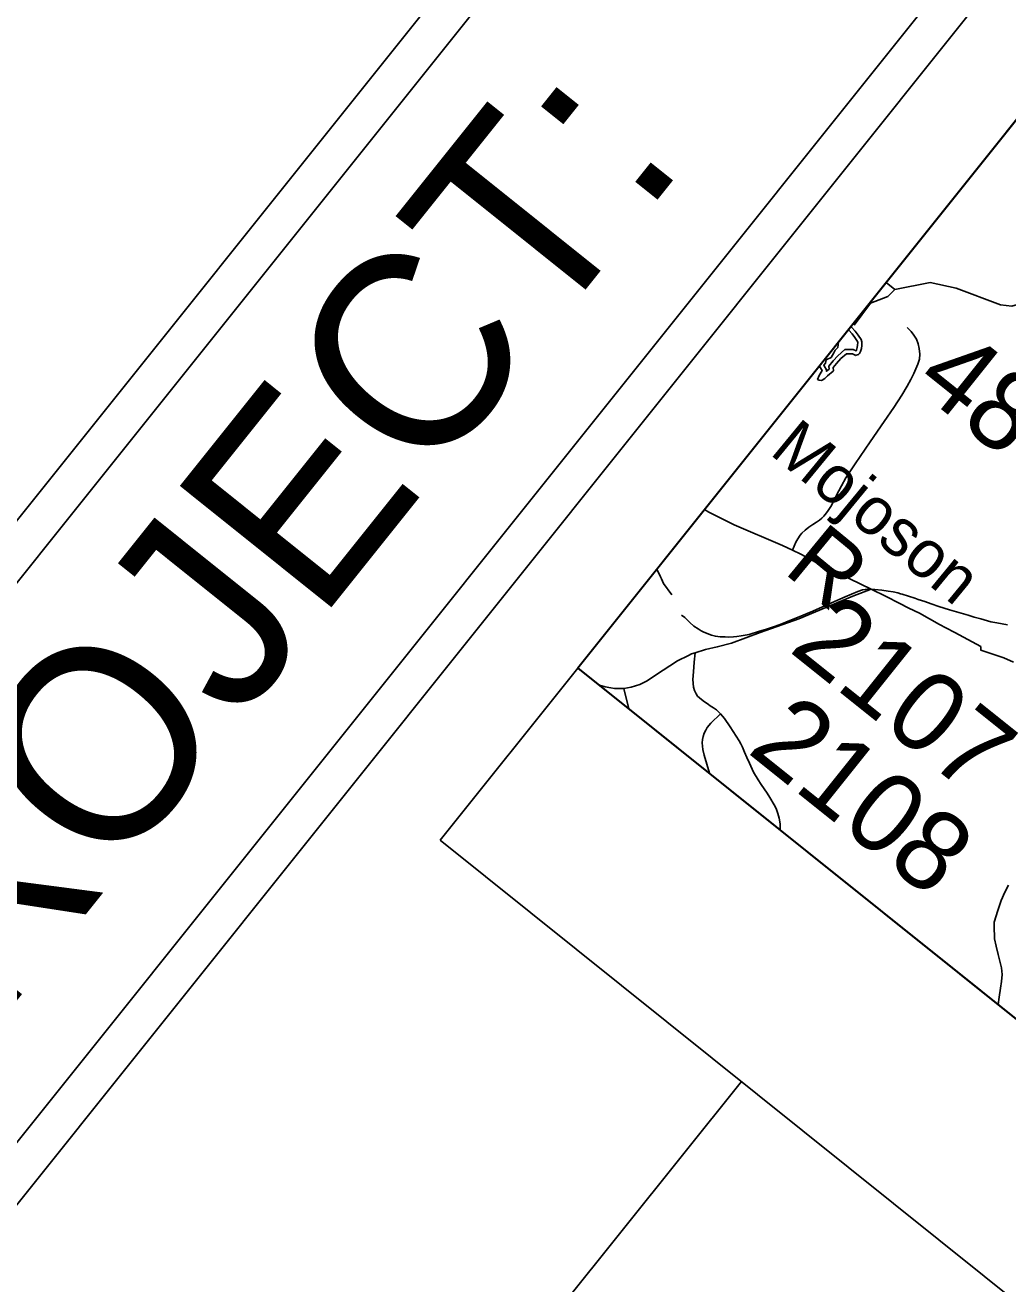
# Model space of a CAD drawing. Extents: x 1732765 to 1738218, y 913652 to 917906.
# Drawn here: x 1733949.3 to 1734202.3, y 916756.7 to 917080.6 of the extents above; entities that cross this region are included whole.
import ezdxf

# ---------------------------------------------------------------- set-up
doc = ezdxf.new("R2010")
doc.units = 0
for name, color, linetype in [('Old_Level_28', 7, 'Continuous'), ('Old_Level_32', 7, 'Continuous'), ('Old_Level_34', 7, 'Continuous'), ('Old_Level_44', 7, 'Continuous'), ('Old_Level_48', 7, 'Continuous'), ('Old_Level_49', 7, 'Continuous'), ('Old_Level_59', 7, 'Continuous'), ('Old_Level_61', 7, 'Continuous'), ('Old_Level_8', 7, 'Continuous'), ('Sheet Title CELL', 7, 'Continuous')]:
    doc.layers.add(name, color=color, linetype=linetype)

msp = doc.modelspace()

# ---------------------------------------------------------------- linework, layer by layer
at = {"layer": 'Old_Level_28'}
for points in [[(1734124.18, 916955.89), (1734125.35, 916955.24), (1734131.89, 916952.02), (1734144.32, 916946.66), (1734146.88, 916945.47)], [(1734146.88, 916945.47), (1734149.04, 916944.47), (1734153.01, 916942.31), (1734155.94, 916940.88), (1734167.13, 916935.46)], [(1734167.13, 916935.46), (1734170.98, 916933.51), (1734174.31, 916931.87), (1734176.81, 916930.58), (1734179.56, 916929.22), (1734184.69, 916926.37), (1734186.39, 916925.52), (1734188.68, 916924.28), (1734195.34, 916920.68), (1734195.36, 916919.72), (1734201.24, 916917.77), (1734203.78, 916916.69)]]:
    msp.add_lwpolyline(points, dxfattribs=at)
at = {"layer": 'Old_Level_32'}
for points in [[(1734146.88, 916945.47), (1734147.77, 916947.51), (1734148.28, 916948.41), (1734148.85, 916949.3), (1734149.3, 916949.85), (1734150.11, 916950.6), (1734151.07, 916951.39), (1734152.09, 916952.04), (1734153.06, 916952.66), (1734153.82, 916953.22), (1734154.43, 916953.71), (1734154.96, 916954.23), (1734155.64, 916955.06), (1734156.05, 916955.64), (1734156.88, 916956.95), (1734158.15, 916959.46), (1734159.49, 916962.05), (1734160.61, 916964.05), (1734163.03, 916967.68), (1734166.84, 916973.35), (1734170.47, 916978.59), (1734172.99, 916982.15), (1734174.99, 916985.34), (1734176.36, 916987.64), (1734177.3, 916989.37), (1734178.09, 916990.92), (1734179.17, 916993.33), (1734179.53, 916994.63), (1734179.65, 916995.91), (1734179.51, 916997.34), (1734179.21, 916998.52), (1734178.76, 916999.77), (1734178.15, 917000.77), (1734177.39, 917001.72), (1734176.42, 917002.74)], [(1734121.86, 916919.09), (1734124.51, 916919.89), (1734127.52, 916920.57), (1734131.14, 916921.53), (1734138.55, 916924.28), (1734148.47, 916927.82), (1734162.42, 916933.62), (1734167.13, 916935.46)], [(1734103.44, 916909.84), (1734105.35, 916910.2), (1734107.54, 916910.88), (1734109.5, 916911.84), (1734111.64, 916913.29), (1734117.25, 916917), (1734120.06, 916918.38), (1734120.88, 916918.78), (1734121.86, 916919.09)], [(1734121.86, 916919.09), (1734121.6, 916916.64), (1734121.42, 916914.14), (1734121.25, 916912.23), (1734121.35, 916910.26), (1734121.66, 916909.34), (1734122.06, 916908.52), (1734122.44, 916907.93), (1734122.97, 916907.44), (1734123.91, 916906.68), (1734125.21, 916905.77), (1734125.69, 916905.45), (1734126.56, 916904.9), (1734127.33, 916904.35), (1734128.36, 916903.36)], [(1734097.18, 916910.71), (1734098.62, 916910.29), (1734100.13, 916910.01), (1734101.08, 916909.89), (1734103.44, 916909.84)], [(1734103.44, 916909.84), (1734104.77, 916904.64)], [(1734128.36, 916903.36), (1734125.82, 916900.99), (1734124.9, 916899.84), (1734124.54, 916899.15), (1734124.16, 916898.39), (1734123.91, 916897.51), (1734123.72, 916896.77), (1734123.66, 916895.86), (1734123.82, 916894.21), (1734124.16, 916892.68), (1734125.48, 916888.07)], [(1734128.36, 916903.36), (1734129.35, 916902.12), (1734130.79, 916899.99), (1734133.11, 916896.41), (1734133.57, 916895.64), (1734133.99, 916894.75), (1734134.48, 916893.51), (1734135.1, 916892.12), (1734135.81, 916890.66), (1734136.85, 916888.34), (1734138.03, 916886.36), (1734138.85, 916885.18), (1734140.32, 916882.93), (1734141, 916881.79), (1734142.13, 916879.91), (1734142.63, 916878.98), (1734143.07, 916877.71), (1734143.48, 916876.47), (1734143.7, 916875.03), (1734143.71, 916873.79), (1734143.68, 916873.5)], [(1734202.49, 916859.29), (1734201.55, 916857.49), (1734200.6, 916855.34), (1734199.71, 916852.79), (1734198.79, 916849.79), (1734198.78, 916847.92), (1734198.85, 916846.33), (1734198.89, 916845.45), (1734199.34, 916843.55), (1734199.79, 916841.41), (1734200.37, 916839.37), (1734200.68, 916838.04), (1734200.87, 916836.32), (1734200.66, 916834.52), (1734200.4, 916832.74), (1734200.12, 916830.49), (1734199.79, 916828.6)]]:
    msp.add_lwpolyline(points, dxfattribs=at)
at = {"layer": 'Old_Level_44'}
for points in [[(1734111.97, 916940.62), (1734112.91, 916938.57), (1734113.16, 916938.09), (1734113.66, 916936.9), (1734115.85, 916933.97)], [(1734202.21, 916926.28), (1734199.47, 916926.75), (1734197.92, 916926.99), (1734195.32, 916927.79), (1734193.68, 916928.23), (1734192.08, 916928.73), (1734189.08, 916929.59), (1734187.25, 916930.14), (1734184.52, 916930.99), (1734182.6, 916931.66), (1734180.92, 916932.27), (1734179.23, 916932.78), (1734178.39, 916933.09), (1734175.1, 916934.14), (1734174.71, 916934.27), (1734174, 916934.47), (1734172.8, 916934.74), (1734171.47, 916934.94), (1734169.85, 916935.19), (1734168.09, 916935.35), (1734166.99, 916935.42), (1734166.2, 916935.42), (1734165.64, 916935.37), (1734164.87, 916935.23), (1734163.73, 916934.87), (1734160.41, 916933.47), (1734156.93, 916931.94), (1734152.08, 916929.79), (1734148.18, 916928.15), (1734145.78, 916927.23), (1734144.14, 916926.51), (1734142.28, 916925.84), (1734139.94, 916925.05), (1734138.38, 916924.59), (1734135.71, 916923.81), (1734133.62, 916923.41), (1734132.53, 916923.27), (1734131.68, 916923.2), (1734130.31, 916923.11), (1734129.56, 916923.14), (1734128.24, 916923.13), (1734127.05, 916923.3), (1734126, 916923.56), (1734124.05, 916924.35), (1734123.34, 916924.74), (1734122.55, 916925.2), (1734121.46, 916925.92), (1734120.45, 916926.82), (1734119.67, 916927.6), (1734119.12, 916928.12), (1734118.32, 916928.72)]]:
    msp.add_lwpolyline(points, dxfattribs=at)
at = {"layer": 'Old_Level_48'}
msp.add_lwpolyline([(1734223.86, 917080.44), (1734091.6, 916915.18), (1734247.43, 916790.47)], dxfattribs=at)
at = {"layer": 'Old_Level_49'}
msp.add_lwpolyline([(1734223.86, 917080.44), (1734091.6, 916915.18), (1734247.43, 916790.47)], dxfattribs=at)
at = {"layer": 'Old_Level_59'}
for points in [[(1734162.71, 917003.4), (1734166.98, 917008.99), (1734171.41, 917010.71), (1734173.19, 917012.53)], [(1734170.99, 917014.38), (1734173.19, 917012.53)], [(1734173.19, 917012.53), (1734182.34, 917014.31), (1734188.97, 917012.84), (1734200.45, 917008.63), (1734203.33, 917008.21), (1734210.95, 917010.44), (1734214.2, 917012.08), (1734221.38, 917013.17), (1734227.05, 917013.07), (1734250.36, 917004.87)]]:
    msp.add_lwpolyline(points, dxfattribs=at)
at = {"layer": 'Old_Level_61'}
for points in [[(1734162.1, 917002.85), (1734163.05, 917001.79), (1734163.81, 917000.81), (1734164.54, 916999.67), (1734164.76, 916999.07), (1734164.71, 916998.15), (1734164.61, 916997.34), (1734164.34, 916996.56), (1734164.13, 916996.04), (1734163.85, 916995.83), (1734163.3, 916995.6), (1734163.17, 916995.55), (1734162.28, 916996.01), (1734160.75, 916996), (1734159.33, 916994.75), (1734158.17, 916993.48), (1734157.34, 916992.47), (1734157.43, 916991.64), (1734157.38, 916991.52), (1734155.87, 916990.35), (1734155.18, 916989.63), (1734154.55, 916989.22), (1734154.3, 916989.14), (1734153.74, 916989.2), (1734153.34, 916989.41), (1734153.34, 916989.42), (1734153.77, 916990.45), (1734154.49, 916991.7), (1734153.92, 916992.6), (1734153.69, 916992.75)], [(1734161.38, 917002.05), (1734162.22, 917001.11), (1734162.93, 917000.19), (1734163.57, 916999.19), (1734163.68, 916998.91), (1734163.64, 916998.25), (1734163.56, 916997.58), (1734163.34, 916996.93), (1734163.26, 916996.75), (1734163.23, 916996.73), (1734162.53, 916997.09), (1734160.34, 916997.07), (1734158.58, 916995.51), (1734157.36, 916994.18), (1734156.23, 916992.81), (1734156.31, 916992.05), (1734155.61, 916991.5), (1734155.74, 916991.72), (1734154.91, 916993.05), (1734155.38, 916993.57), (1734155.58, 916994.47), (1734155.69, 916994.53), (1734156.79, 916995.05), (1734157.53, 916996.21)], [(1734161.23, 917002.18), (1734161.38, 917002.05)], [(1734161.91, 917003.03), (1734162.1, 917002.85)], [(1734157.53, 916996.21), (1734157.84, 916996.94), (1734158.54, 916997.6), (1734158.68, 916998.99)]]:
    msp.add_lwpolyline(points, dxfattribs=at)
at = {"layer": 'Sheet Title CELL'}
for p, q in [((1733154.09, 915802.12), (1734428.76, 917394.86)), ((1733393.09, 916084.75), (1734436.57, 917388.61)), ((1734427.31, 917334.59), (1734091.57, 916915.07)), ((1734427.31, 917334.59), (1734091.57, 916915.07)), ((1734091.57, 916915.07), (1734056.15, 916870.82)), ((1734091.57, 916915.07), (1734625.37, 916487.87)), ((1734091.57, 916915.07), (1734625.37, 916487.87)), ((1734091.57, 916915.07), (1734625.37, 916487.87)), ((1734056.15, 916870.82), (1734589.95, 916443.62)), ((1734087.51, 916751), (1734133.72, 916808.74))]:
    msp.add_line(p, q, dxfattribs=at)
for points in [[(1734356.94, 917465.15), (1733069.77, 915856.79)], [(1734356.94, 917465.15), (1733069.77, 915856.79)], [(1734358.52, 917451.08), (1733083.83, 915858.35)]]:
    msp.add_lwpolyline(points, dxfattribs=at)

# ---------------------------------------------------------------- texts
at = {"layer": 'Old_Level_34'}
for s, height, p in [('Mojoson', 12.313, (1734140.71, 916970.37)), ('R', 17.24, (1734144.25, 916939.88))]:
    msp.add_text(s, height=height, rotation=320.5476, dxfattribs=at).set_placement(p)
at = {"layer": 'Old_Level_8'}
for s, p in [('4882', (1734177.66, 916987.71)), ('2107', (1734145.61, 916919.68)), ('2108', (1734134.86, 916893.64))]:
    msp.add_text(s, height=20.505, rotation=321.3297, dxfattribs=at).set_placement(p)
at = {"layer": 'Sheet Title CELL'}
msp.add_text('TIP PROJECT:', height=49.9999, rotation=51.3297, dxfattribs=at).set_placement((1733836.74, 916691.55))

doc.saveas('drawing.dxf')
